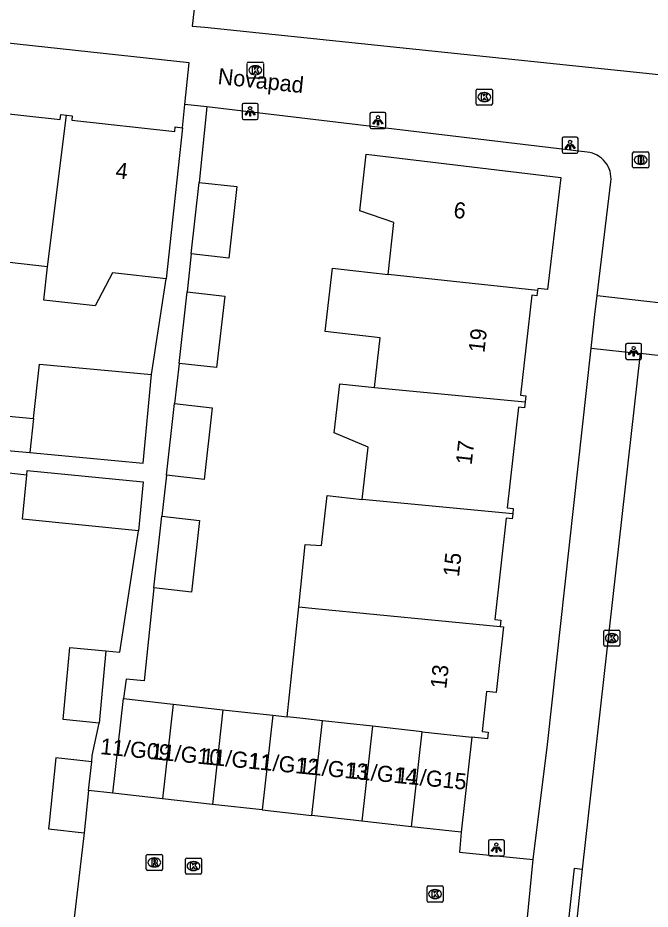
# Model space of a CAD drawing. Extents: x 162398 to 163643, y 386453 to 387397.
# Drawn here: x 162539.1 to 162578.5, y 386510.9 to 386566.4 of the extents above; entities that cross this region are included whole.
import ezdxf

# ---------------------------------------------------------------- set-up
doc = ezdxf.new("R2010")
doc.units = 0
for name, color, linetype in [('IMGEO_Brandkraan', 7, 'Continuous'), ('IMGEO_Kolk', 7, 'Continuous'), ('IMGEO_Lichtpunt', 7, 'Continuous'), ('IMGEO_Openbare_ruimte_label', 7, 'Continuous'), ('IMGEO_Pand', 7, 'Continuous'), ('IMGEO_Pand_nummerreeks', 7, 'Continuous'), ('IMGEO_Rijbaan_lokaal_open', 7, 'Continuous'), ('IMGEO_Rioolput', 7, 'Continuous'), ('IMGEO_Voetpad_open', 7, 'Continuous')]:
    doc.layers.add(name, color=color, linetype=linetype)

msp = doc.modelspace()

# ---------------------------------------------------------------- linework, layer by layer
at = {"layer": 'IMGEO_Brandkraan'}
for p, q in [((162577.363, 386557.099), (162577.363, 386557.951)), ((162577.438, 386558.025), (162578.29, 386558.025)), ((162577.851, 386557.805), (162577.876, 386557.805)), ((162578.364, 386557.951), (162578.364, 386557.099)), ((162578.29, 386557.025), (162577.438, 386557.025)), ((162577.874, 386557.245), (162577.849, 386557.245))]:
    msp.add_line(p, q, dxfattribs=at)
for points in [[(162577.363, 386557.099), (162577.363, 386557.951)], [(162577.438, 386558.025), (162578.29, 386558.025)], [(162577.711, 386557.725), (162577.711, 386557.325), (162577.924, 386557.325)], [(162577.942, 386557.725), (162577.711, 386557.725)], [(162577.89, 386557.644), (162577.836, 386557.644), (162577.836, 386557.568)], [(162577.836, 386557.568), (162577.889, 386557.568)], [(162578.364, 386557.951), (162578.364, 386557.099)], [(162578.29, 386557.025), (162577.438, 386557.025)], [(162577.898, 386557.492), (162577.836, 386557.492), (162577.836, 386557.411)], [(162577.836, 386557.411), (162577.898, 386557.411)]]:
    msp.add_lwpolyline(points, dxfattribs=at)
for centre, radius, start, end in [((162577.44, 386557.949), 0.0765, 91.552, 178.448), ((162577.44, 386557.949), 0.0765, 91.552, 178.448), ((162577.891, 386557.606), 0.0379, 267.8285, 90.9355), ((162577.946, 386557.58), 0.145, 59.4692, 91.5367), ((162577.971, 386557.627), 0.0922, 285.5137, 58.1501), ((162577.976, 386557.435), 0.105, 301.3115, 78.989), ((162578.288, 386557.949), 0.0765, 1.552, 88.448), ((162578.288, 386557.949), 0.0765, 1.552, 88.448), ((162577.44, 386557.101), 0.0765, 181.552, 268.448), ((162577.44, 386557.101), 0.0765, 181.552, 268.448), ((162577.899, 386557.451), 0.0404, 269.8759, 90.5077), ((162577.93, 386557.576), 0.251, 268.6676, 293.5347), ((162578.288, 386557.101), 0.0765, 271.552, 358.448), ((162578.288, 386557.101), 0.0765, 271.552, 358.448)]:
    msp.add_arc(centre, radius, start, end, dxfattribs=at)
for centre, major_axis, ratio, start_param, end_param in [((162577.85, 386557.525), (-0.387, 0.002), 0.722429, 4.712389, 7.853982), ((162577.875, 386557.525), (-0.39, 0.002), 0.717154, 1.570796, 4.712389)]:
    msp.add_ellipse(centre, major_axis=major_axis, ratio=ratio, start_param=start_param, end_param=end_param, dxfattribs=at)
at = {"layer": 'IMGEO_Kolk'}
for p, q in [((162553.47, 386563.605), (162554.322, 386563.605)), ((162553.395, 386562.679), (162553.395, 386563.531)), ((162553.883, 386563.385), (162553.908, 386563.385)), ((162554.396, 386563.531), (162554.396, 386562.679)), ((162554.322, 386562.605), (162553.47, 386562.605)), ((162553.906, 386562.825), (162553.881, 386562.825)), ((162567.636, 386561.005), (162567.636, 386561.857)), ((162567.711, 386561.931), (162568.563, 386561.931)), ((162568.124, 386561.711), (162568.149, 386561.711)), ((162568.637, 386561.857), (162568.637, 386561.005)), ((162568.563, 386560.931), (162567.711, 386560.931)), ((162568.147, 386561.151), (162568.122, 386561.151)), ((162575.569, 386527.369), (162575.569, 386528.221)), ((162575.644, 386528.295), (162576.496, 386528.295)), ((162576.57, 386528.221), (162576.57, 386527.369)), ((162576.057, 386528.075), (162576.082, 386528.075)), ((162576.496, 386527.295), (162575.644, 386527.295)), ((162576.08, 386527.515), (162576.055, 386527.515)), ((162549.552, 386513.197), (162549.552, 386514.049)), ((162549.627, 386514.123), (162550.479, 386514.123)), ((162550.04, 386513.903), (162550.065, 386513.903)), ((162550.553, 386514.049), (162550.553, 386513.197)), ((162550.063, 386513.343), (162550.038, 386513.343)), ((162550.479, 386513.123), (162549.627, 386513.123)), ((162564.574, 386511.46), (162564.574, 386512.312)), ((162564.649, 386512.386), (162565.501, 386512.386)), ((162565.062, 386512.166), (162565.087, 386512.166)), ((162565.575, 386512.312), (162565.575, 386511.46)), ((162565.085, 386511.606), (162565.06, 386511.606)), ((162565.501, 386511.386), (162564.649, 386511.386))]:
    msp.add_line(p, q, dxfattribs=at)
for points in [[(162553.47, 386563.605), (162554.322, 386563.605)], [(162553.395, 386562.679), (162553.395, 386563.531)], [(162553.716, 386563.305), (162553.839, 386563.305), (162553.839, 386563.154), (162553.969, 386563.305), (162554.133, 386563.305), (162553.987, 386563.154), (162554.14, 386562.905), (162553.988, 386562.905), (162553.903, 386563.069), (162553.839, 386563.002), (162553.839, 386562.905), (162553.716, 386562.905), (162553.716, 386563.305)], [(162554.396, 386563.531), (162554.396, 386562.679)], [(162554.322, 386562.605), (162553.47, 386562.605)], [(162567.636, 386561.005), (162567.636, 386561.857)], [(162567.711, 386561.931), (162568.563, 386561.931)], [(162567.957, 386561.631), (162568.08, 386561.631), (162568.08, 386561.48), (162568.21, 386561.631), (162568.374, 386561.631), (162568.228, 386561.48), (162568.381, 386561.231), (162568.229, 386561.231), (162568.144, 386561.395), (162568.08, 386561.328), (162568.08, 386561.231), (162567.957, 386561.231), (162567.957, 386561.631)], [(162568.637, 386561.857), (162568.637, 386561.005)], [(162568.563, 386560.931), (162567.711, 386560.931)], [(162575.569, 386527.369), (162575.569, 386528.221)], [(162575.644, 386528.295), (162576.496, 386528.295)], [(162576.57, 386528.221), (162576.57, 386527.369)], [(162575.89, 386527.995), (162576.013, 386527.995), (162576.013, 386527.844), (162576.143, 386527.995), (162576.307, 386527.995), (162576.161, 386527.844), (162576.314, 386527.595), (162576.162, 386527.595), (162576.077, 386527.759), (162576.013, 386527.692), (162576.013, 386527.595), (162575.89, 386527.595), (162575.89, 386527.995)], [(162576.496, 386527.295), (162575.644, 386527.295)], [(162549.552, 386513.197), (162549.552, 386514.049)], [(162549.627, 386514.123), (162550.479, 386514.123)], [(162549.873, 386513.823), (162549.996, 386513.823), (162549.996, 386513.672), (162550.126, 386513.823), (162550.29, 386513.823), (162550.144, 386513.672), (162550.297, 386513.423), (162550.145, 386513.423), (162550.06, 386513.587), (162549.996, 386513.52), (162549.996, 386513.423), (162549.873, 386513.423), (162549.873, 386513.823)], [(162550.553, 386514.049), (162550.553, 386513.197)], [(162550.479, 386513.123), (162549.627, 386513.123)], [(162564.574, 386511.46), (162564.574, 386512.312)], [(162564.649, 386512.386), (162565.501, 386512.386)], [(162564.895, 386512.086), (162565.018, 386512.086), (162565.018, 386511.935), (162565.148, 386512.086), (162565.312, 386512.086), (162565.166, 386511.935), (162565.319, 386511.686), (162565.167, 386511.686), (162565.082, 386511.85), (162565.018, 386511.783), (162565.018, 386511.686), (162564.895, 386511.686), (162564.895, 386512.086)], [(162565.575, 386512.312), (162565.575, 386511.46)], [(162565.501, 386511.386), (162564.649, 386511.386)]]:
    msp.add_lwpolyline(points, dxfattribs=at)
for centre, start, end in [((162553.472, 386563.529), 91.552, 178.448), ((162553.472, 386563.529), 91.552, 178.448), ((162554.32, 386563.529), 1.552, 88.448), ((162554.32, 386563.529), 1.552, 88.448), ((162553.472, 386562.681), 181.552, 268.448), ((162553.472, 386562.681), 181.552, 268.448), ((162554.32, 386562.681), 271.552, 358.448), ((162554.32, 386562.681), 271.552, 358.448), ((162567.713, 386561.855), 91.552, 178.448), ((162567.713, 386561.855), 91.552, 178.448), ((162568.561, 386561.855), 1.552, 88.448), ((162568.561, 386561.855), 1.552, 88.448), ((162567.713, 386561.007), 181.552, 268.448), ((162567.713, 386561.007), 181.552, 268.448), ((162568.561, 386561.007), 271.552, 358.448), ((162568.561, 386561.007), 271.552, 358.448), ((162575.646, 386528.219), 91.552, 178.448), ((162575.646, 386528.219), 91.552, 178.448), ((162576.494, 386528.219), 1.552, 88.448), ((162576.494, 386528.219), 1.552, 88.448), ((162575.646, 386527.371), 181.552, 268.448), ((162575.646, 386527.371), 181.552, 268.448), ((162576.494, 386527.371), 271.552, 358.448), ((162576.494, 386527.371), 271.552, 358.448), ((162549.629, 386514.047), 91.552, 178.448), ((162549.629, 386514.047), 91.552, 178.448), ((162550.477, 386514.047), 1.552, 88.448), ((162550.477, 386514.047), 1.552, 88.448), ((162549.629, 386513.199), 181.552, 268.448), ((162549.629, 386513.199), 181.552, 268.448), ((162550.477, 386513.199), 271.552, 358.448), ((162550.477, 386513.199), 271.552, 358.448), ((162564.651, 386512.31), 91.552, 178.448), ((162564.651, 386512.31), 91.552, 178.448), ((162565.499, 386512.31), 1.552, 88.448), ((162565.499, 386512.31), 1.552, 88.448), ((162564.651, 386511.462), 181.552, 268.448), ((162564.651, 386511.462), 181.552, 268.448), ((162565.499, 386511.462), 271.552, 358.448), ((162565.499, 386511.462), 271.552, 358.448)]:
    msp.add_arc(centre, 0.0765, start, end, dxfattribs=at)
for centre, major_axis, ratio, start_param, end_param in [((162553.882, 386563.105), (-0.387, 0.002), 0.722429, 4.712389, 7.853982), ((162553.907, 386563.105), (-0.39, 0.002), 0.717154, 1.570796, 4.712389), ((162568.123, 386561.431), (-0.387, 0.002), 0.722429, 4.712389, 7.853982), ((162568.148, 386561.431), (-0.39, 0.002), 0.717154, 1.570796, 4.712389), ((162576.056, 386527.795), (-0.387, 0.002), 0.722429, 4.712389, 7.853982), ((162576.081, 386527.795), (-0.39, 0.002), 0.717154, 1.570796, 4.712389), ((162550.039, 386513.623), (-0.387, 0.002), 0.722429, 4.712389, 7.853982), ((162550.064, 386513.623), (-0.39, 0.002), 0.717154, 1.570796, 4.712389), ((162565.061, 386511.886), (-0.387, 0.002), 0.722429, 4.712389, 7.853982), ((162565.086, 386511.886), (-0.39, 0.002), 0.717154, 1.570796, 4.712389)]:
    msp.add_ellipse(centre, major_axis=major_axis, ratio=ratio, start_param=start_param, end_param=end_param, dxfattribs=at)
at = {"layer": 'IMGEO_Lichtpunt'}
for p, q in [((162553.073, 386560.944), (162553.073, 386560.137)), ((162553.073, 386560.944), (162553.073, 386560.137)), ((162553.975, 386561.039), (162553.167, 386561.039)), ((162553.975, 386561.039), (162553.167, 386561.039)), ((162554.069, 386560.137), (162554.069, 386560.944)), ((162554.069, 386560.137), (162554.069, 386560.944)), ((162561.025, 386560.383), (162561.025, 386559.576)), ((162561.025, 386560.383), (162561.025, 386559.576)), ((162561.927, 386560.478), (162561.119, 386560.478)), ((162561.927, 386560.478), (162561.119, 386560.478)), ((162562.021, 386559.576), (162562.021, 386560.383)), ((162562.021, 386559.576), (162562.021, 386560.383)), ((162553.167, 386560.043), (162553.975, 386560.043)), ((162553.167, 386560.043), (162553.975, 386560.043)), ((162561.119, 386559.482), (162561.927, 386559.482)), ((162561.119, 386559.482), (162561.927, 386559.482)), ((162572.974, 386558.849), (162572.974, 386558.042)), ((162572.974, 386558.849), (162572.974, 386558.042)), ((162573.876, 386558.944), (162573.068, 386558.944)), ((162573.876, 386558.944), (162573.068, 386558.944)), ((162573.97, 386558.042), (162573.97, 386558.849)), ((162573.97, 386558.042), (162573.97, 386558.849)), ((162573.068, 386557.948), (162573.876, 386557.948)), ((162573.068, 386557.948), (162573.876, 386557.948)), ((162576.926, 386546.028), (162576.926, 386545.221)), ((162576.926, 386546.028), (162576.926, 386545.221)), ((162577.828, 386546.123), (162577.02, 386546.123)), ((162577.828, 386546.123), (162577.02, 386546.123)), ((162577.922, 386545.221), (162577.922, 386546.028)), ((162577.922, 386545.221), (162577.922, 386546.028)), ((162577.02, 386545.127), (162577.828, 386545.127)), ((162577.02, 386545.127), (162577.828, 386545.127)), ((162568.389, 386515.163), (162568.389, 386514.356)), ((162568.389, 386515.163), (162568.389, 386514.356)), ((162569.291, 386515.258), (162568.483, 386515.258)), ((162569.291, 386515.258), (162568.483, 386515.258)), ((162569.385, 386514.356), (162569.385, 386515.163)), ((162569.385, 386514.356), (162569.385, 386515.163)), ((162568.483, 386514.262), (162569.291, 386514.262)), ((162568.483, 386514.262), (162569.291, 386514.262))]:
    msp.add_line(p, q, dxfattribs=at)
for points in [[(162553.447, 386560.608), (162553.486, 386560.58), (162553.298, 386560.318), (162553.26, 386560.345), (162553.447, 386560.608)], [(162553.549, 386560.56), (162553.596, 386560.56), (162553.596, 386560.238), (162553.549, 386560.238), (162553.549, 386560.56)], [(162553.659, 386560.58), (162553.697, 386560.607), (162553.884, 386560.345), (162553.845, 386560.317), (162553.659, 386560.58)], [(162561.399, 386560.047), (162561.438, 386560.019), (162561.25, 386559.757), (162561.212, 386559.784), (162561.399, 386560.047)], [(162561.501, 386559.999), (162561.548, 386559.999), (162561.548, 386559.677), (162561.501, 386559.677), (162561.501, 386559.999)], [(162561.611, 386560.019), (162561.649, 386560.046), (162561.836, 386559.784), (162561.797, 386559.756), (162561.611, 386560.019)], [(162573.348, 386558.513), (162573.387, 386558.485), (162573.199, 386558.223), (162573.161, 386558.25), (162573.348, 386558.513)], [(162573.45, 386558.465), (162573.497, 386558.465), (162573.497, 386558.143), (162573.45, 386558.143), (162573.45, 386558.465)], [(162573.56, 386558.485), (162573.598, 386558.512), (162573.785, 386558.25), (162573.746, 386558.222), (162573.56, 386558.485)], [(162577.3, 386545.692), (162577.339, 386545.664), (162577.151, 386545.402), (162577.113, 386545.429), (162577.3, 386545.692)], [(162577.402, 386545.644), (162577.449, 386545.644), (162577.449, 386545.322), (162577.402, 386545.322), (162577.402, 386545.644)], [(162577.512, 386545.664), (162577.55, 386545.691), (162577.737, 386545.429), (162577.698, 386545.401), (162577.512, 386545.664)], [(162568.763, 386514.827), (162568.802, 386514.799), (162568.614, 386514.537), (162568.576, 386514.564), (162568.763, 386514.827)], [(162568.865, 386514.779), (162568.912, 386514.779), (162568.912, 386514.457), (162568.865, 386514.457), (162568.865, 386514.779)], [(162568.975, 386514.799), (162569.013, 386514.826), (162569.2, 386514.564), (162569.161, 386514.536), (162568.975, 386514.799)]]:
    msp.add_lwpolyline(points, dxfattribs=at)
for centre in [(162553.572, 386560.742), (162561.524, 386560.181), (162573.473, 386558.647), (162577.425, 386545.826), (162568.888, 386514.961)]:
    msp.add_circle(centre, 0.0994, dxfattribs=at)
for centre, start, end in [((162553.167, 386560.944), 90, 180), ((162553.167, 386560.944), 90, 180), ((162553.975, 386560.944), 0, 90), ((162553.975, 386560.944), 0, 90), ((162561.119, 386560.383), 90, 180), ((162561.119, 386560.383), 90, 180), ((162561.927, 386560.383), 0, 90), ((162561.927, 386560.383), 0, 90), ((162553.167, 386560.137), 180, 270), ((162553.167, 386560.137), 180, 270), ((162553.975, 386560.137), 270, 0), ((162553.975, 386560.137), 270, 360), ((162561.119, 386559.576), 180, 270), ((162561.119, 386559.576), 180, 270), ((162561.927, 386559.576), 270, 0), ((162561.927, 386559.576), 270, 360), ((162573.068, 386558.849), 90, 180), ((162573.068, 386558.849), 90, 180), ((162573.876, 386558.849), 0, 90), ((162573.876, 386558.849), 0, 90), ((162573.068, 386558.042), 180, 270), ((162573.068, 386558.042), 180, 270), ((162573.876, 386558.042), 270, 0), ((162573.876, 386558.042), 270, 360), ((162577.02, 386546.028), 90, 180), ((162577.02, 386546.028), 90, 180), ((162577.828, 386546.028), 0, 90), ((162577.828, 386546.028), 0, 90), ((162577.02, 386545.221), 180, 270), ((162577.02, 386545.221), 180, 270), ((162577.828, 386545.221), 270, 0), ((162577.828, 386545.221), 270, 360), ((162568.483, 386515.163), 90, 180), ((162568.483, 386515.163), 90, 180), ((162569.291, 386515.163), 0, 90), ((162569.291, 386515.163), 0, 90), ((162568.483, 386514.356), 180, 270), ((162568.483, 386514.356), 180, 270), ((162569.291, 386514.356), 270, 0), ((162569.291, 386514.356), 270, 360)]:
    msp.add_arc(centre, 0.0946, start, end, dxfattribs=at)
at = {"layer": 'IMGEO_Pand'}
for points in [[(162535.215, 386561.072), (162535.544, 386561.036), (162535.51, 386560.724), (162541.769, 386560.039), (162541.803, 386560.351), (162542.158, 386560.312)], [(162540.967, 386550.888), (162542.158, 386560.312)], [(162542.158, 386560.312), (162542.512, 386560.273), (162542.481, 386559.989), (162548.88, 386559.289), (162548.911, 386559.576), (162549.373, 386559.526)], [(162549.373, 386559.526), (162548.829, 386554.556), (162548.346, 386550.142)], [(162562.149, 386550.408), (162562.512, 386553.645), (162560.395, 386554.356), (162560.791, 386557.887), (162572.905, 386556.438), (162572.071, 386549.468), (162571.463, 386549.54), (162571.447, 386549.4)], [(162550.407, 386556.13), (162552.744, 386555.866), (162552.241, 386551.42), (162549.904, 386551.684)], [(162549.904, 386551.684), (162550.407, 386556.13)], [(162540.967, 386550.888), (162537.679, 386551.247), (162536.966, 386549.168), (162533.949, 386549.498)], [(162548.346, 386550.142), (162545.019, 386550.506), (162543.942, 386548.46), (162540.74, 386548.81), (162540.967, 386550.888)], [(162561.304, 386543.369), (162561.652, 386546.473), (162558.246, 386546.854), (162558.688, 386550.796), (162559.954, 386550.654), (162562.149, 386550.408)], [(162571.447, 386549.4), (162562.149, 386550.408)], [(162549.657, 386549.324), (162551.994, 386549.06), (162551.491, 386544.614), (162549.154, 386544.878)], [(162549.154, 386544.878), (162549.657, 386549.324)], [(162571.447, 386549.4), (162571.411, 386549.073), (162571.085, 386549.11), (162570.389, 386542.897), (162570.727, 386542.859), (162570.685, 386542.488)], [(162540.097, 386541.459), (162540.465, 386544.831), (162547.435, 386544.188)], [(162539.864, 386539.328), (162546.926, 386538.676), (162547.435, 386544.188)], [(162560.549, 386536.414), (162560.912, 386539.658), (162558.805, 386540.56), (162559.147, 386543.61), (162561.304, 386543.369)], [(162561.304, 386543.369), (162570.685, 386542.488)], [(162548.875, 386542.374), (162551.212, 386542.11), (162550.709, 386537.664), (162548.372, 386537.928)], [(162548.372, 386537.928), (162548.875, 386542.374)], [(162570.685, 386542.488), (162570.643, 386542.115), (162570.256, 386542.159), (162569.555, 386535.895), (162569.939, 386535.852), (162569.902, 386535.525)], [(162535.218, 386539.757), (162535.415, 386541.892), (162540.097, 386541.459)], [(162540.097, 386541.459), (162539.864, 386539.328)], [(162535.218, 386539.757), (162539.864, 386539.328)], [(162539.677, 386537.919), (162539.707, 386538.225), (162546.922, 386537.511), (162546.621, 386534.475)], [(162546.621, 386534.475), (162539.406, 386535.189), (162539.677, 386537.919)], [(162556.597, 386529.741), (162557, 386533.607), (162558.018, 386533.549), (162558.366, 386536.658), (162560.549, 386536.414)], [(162569.902, 386535.525), (162560.549, 386536.414)], [(162548.091, 386535.369), (162550.428, 386535.105), (162549.925, 386530.659), (162547.588, 386530.923)], [(162547.588, 386530.923), (162548.091, 386535.369)], [(162569.902, 386535.525), (162569.866, 386535.202), (162569.496, 386535.243), (162568.791, 386528.949), (162569.161, 386528.907), (162569.117, 386528.518)], [(162555.884, 386522.899), (162556.597, 386529.741)], [(162556.597, 386529.741), (162557.61, 386529.642), (162569.117, 386528.518)], [(162569.117, 386528.518), (162569.337, 386528.493), (162568.879, 386524.405), (162568.282, 386524.471), (162568.004, 386521.987), (162568.381, 386521.945), (162568.334, 386521.527), (162567.368, 386521.635)], [(162544.182, 386522.518), (162541.942, 386522.728), (162542.362, 386527.211), (162544.602, 386527.001)], [(162544.602, 386527.001), (162544.182, 386522.518)], [(162545.034, 386518.151), (162545.693, 386524.04)], [(162545.693, 386524.04), (162548.789, 386523.693)], [(162548.789, 386523.693), (162548.13, 386517.804)], [(162548.789, 386523.693), (162551.885, 386523.346)], [(162551.885, 386523.346), (162551.226, 386517.458)], [(162551.885, 386523.346), (162554.981, 386523)], [(162554.981, 386523), (162554.322, 386517.111)], [(162554.981, 386523), (162555.884, 386522.899)], [(162558.078, 386522.655), (162556.844, 386522.791), (162555.884, 386522.899)], [(162557.418, 386516.764), (162558.078, 386522.655)], [(162561.174, 386522.315), (162558.078, 386522.655)], [(162561.174, 386522.315), (162560.514, 386516.417)], [(162564.271, 386521.975), (162561.174, 386522.315)], [(162563.61, 386516.071), (162564.271, 386521.975)], [(162564.271, 386521.975), (162567.368, 386521.635)], [(162567.368, 386521.635), (162566.706, 386515.724)], [(162543.719, 386520.109), (162541.499, 386520.358), (162541.071, 386516.285), (162541.034, 386515.933), (162543.256, 386515.7)], [(162543.53, 386518.312), (162543.719, 386520.109)], [(162543.53, 386518.312), (162543.256, 386515.7)], [(162548.13, 386517.804), (162545.034, 386518.151)], [(162551.226, 386517.458), (162548.13, 386517.804)], [(162554.322, 386517.111), (162551.226, 386517.458)], [(162554.322, 386517.111), (162557.418, 386516.764)], [(162560.514, 386516.417), (162557.418, 386516.764)], [(162563.61, 386516.071), (162560.514, 386516.417)], [(162566.706, 386515.724), (162563.61, 386516.071)]]:
    msp.add_lwpolyline(points, dxfattribs=at)
at = {"layer": 'IMGEO_Rijbaan_lokaal_open'}
for points in [[(162577.823, 386545.5), (162574.232, 386513.437)], [(162643.999, 386538.038), (162577.823, 386545.5)], [(162545.034, 386518.151), (162543.53, 386518.312)], [(162543.256, 386515.7), (162542.63, 386510.403)], [(162566.706, 386515.724), (162566.584, 386514.489), (162571.178, 386514.042)], [(162570.602, 386508.097), (162571.178, 386514.042)], [(162574.232, 386513.437), (162573.651, 386507.959)]]:
    msp.add_lwpolyline(points, dxfattribs=at)
at = {"layer": 'IMGEO_Rioolput'}
for p, q in [((162547.192, 386514.348), (162548.044, 386514.348)), ((162547.117, 386513.422), (162547.117, 386514.274)), ((162547.605, 386514.128), (162547.63, 386514.128)), ((162548.118, 386514.274), (162548.118, 386513.422)), ((162548.044, 386513.348), (162547.192, 386513.348)), ((162547.628, 386513.568), (162547.603, 386513.568))]:
    msp.add_line(p, q, dxfattribs=at)
for points in [[(162547.192, 386514.348), (162548.044, 386514.348)], [(162547.117, 386513.422), (162547.117, 386514.274)], [(162547.706, 386514.046), (162547.454, 386514.048), (162547.454, 386513.648)], [(162547.454, 386513.648), (162547.578, 386513.648), (162547.578, 386513.81), (162547.589, 386513.81)], [(162547.632, 386513.967), (162547.578, 386513.967), (162547.578, 386513.886)], [(162547.578, 386513.886), (162547.63, 386513.886)], [(162547.636, 386513.781), (162547.707, 386513.648), (162547.847, 386513.648), (162547.782, 386513.774)], [(162548.118, 386514.274), (162548.118, 386513.422)], [(162548.044, 386513.348), (162547.192, 386513.348)]]:
    msp.add_lwpolyline(points, dxfattribs=at)
for centre, radius, start, end in [((162547.194, 386514.272), 0.0765, 91.552, 178.448), ((162547.194, 386514.272), 0.0765, 91.552, 178.448), ((162548.042, 386514.272), 0.0765, 1.552, 88.448), ((162548.042, 386514.272), 0.0765, 1.552, 88.448), ((162547.588, 386513.757), 0.0533, 26.0293, 88.6989), ((162547.614, 386514.075), 0.19, 274.7715, 282.9687), ((162547.638, 386513.871), 0.0964, 77.0061, 93.1865), ((162547.652, 386513.928), 0.0378, 276.6634, 79.6772), ((162547.705, 386513.936), 0.109, 350.3612, 89.416), ((162547.703, 386513.936), 0.112, 277.5842, 350.9817), ((162547.687, 386513.721), 0.108, 29.5134, 73.7905), ((162547.194, 386513.424), 0.0765, 181.552, 268.448), ((162547.194, 386513.424), 0.0765, 181.552, 268.448), ((162548.042, 386513.424), 0.0765, 271.552, 358.448), ((162548.042, 386513.424), 0.0765, 271.552, 358.448)]:
    msp.add_arc(centre, radius, start, end, dxfattribs=at)
for centre, major_axis, ratio, start_param, end_param in [((162547.604, 386513.848), (-0.387, 0.002), 0.722429, 4.712389, 7.853982), ((162547.629, 386513.848), (-0.39, 0.002), 0.717154, 1.570796, 4.712389)]:
    msp.add_ellipse(centre, major_axis=major_axis, ratio=ratio, start_param=start_param, end_param=end_param, dxfattribs=at)
at = {"layer": 'IMGEO_Voetpad_open'}
for points in [[(162550.287, 386568.543), (162549.978, 386565.851), (162550.761, 386565.77), (162588.742, 386561.821)], [(162549.509, 386560.977), (162549.788, 386563.56), (162526.646, 386566.068)], [(162549.373, 386559.526), (162549.509, 386560.977)], [(162550.87, 386560.831), (162549.509, 386560.977)], [(162550.87, 386560.831), (162550.407, 386556.13)], [(162574.538, 386558.007), (162550.87, 386560.831)], [(162575.154, 386549.09), (162576.011, 386556.173)], [(162549.904, 386551.684), (162549.657, 386549.324)], [(162547.435, 386544.188), (162548.346, 386550.142)], [(162574.783, 386545.83), (162575.012, 386547.916), (162575.154, 386549.09)], [(162575.154, 386549.09), (162595.86, 386546.731), (162595.881, 386546.745)], [(162571.178, 386514.042), (162572.071, 386521.176), (162574.783, 386545.83)], [(162574.783, 386545.83), (162577.823, 386545.5)], [(162549.154, 386544.878), (162548.875, 386542.374)], [(162539.677, 386537.919), (162521.748, 386539.902)], [(162548.372, 386537.928), (162548.091, 386535.369)], [(162544.602, 386527.001), (162545.478, 386526.922), (162546.621, 386534.475)], [(162547.588, 386530.923), (162546.99, 386525.139), (162545.856, 386525.247), (162545.693, 386524.04)], [(162543.719, 386520.109), (162543.759, 386520.491), (162544.182, 386522.518)], [(162573.651, 386507.959), (162573.155, 386508.016), (162573.736, 386513.494), (162574.232, 386513.437)]]:
    msp.add_lwpolyline(points, dxfattribs=at)
msp.add_arc((162574.36, 386556.356), 1.661, 353.6784, 83.8618, dxfattribs=at)

# ---------------------------------------------------------------- texts
at = {"layer": 'IMGEO_Openbare_ruimte_label'}
msp.add_text('Novapad', height=1, rotation=353.856, dxfattribs=at).set_placement((162551.526, 386562.248))
at = {"layer": 'IMGEO_Pand_nummerreeks'}
for s, rotation, p in [('4', 353.7563, (162545.172, 386556.395)), ('6', 353.179, (162566.186, 386553.939)), ('19', 83.5201, (162568.14, 386545.507)), ('17', 83.5193, (162567.349, 386538.54)), ('15', 83.5201, (162566.557, 386531.574)), ('13', 83.5201, (162565.766, 386524.608)), ('11/G09', 354.4278, (162544.22, 386520.587)), ('11/G10', 354.4278, (162547.368, 386520.28)), ('11/G11', 354.4278, (162550.525, 386519.972)), ('11/G12', 354.4251, (162553.46, 386519.686)), ('11/G13', 354.4278, (162556.517, 386519.387)), ('11/G14', 354.4278, (162559.567, 386519.089)), ('11/G15', 354.4278, (162562.618, 386518.792))]:
    msp.add_text(s, height=1, rotation=rotation, dxfattribs=at).set_placement(p)

doc.saveas('drawing.dxf')
